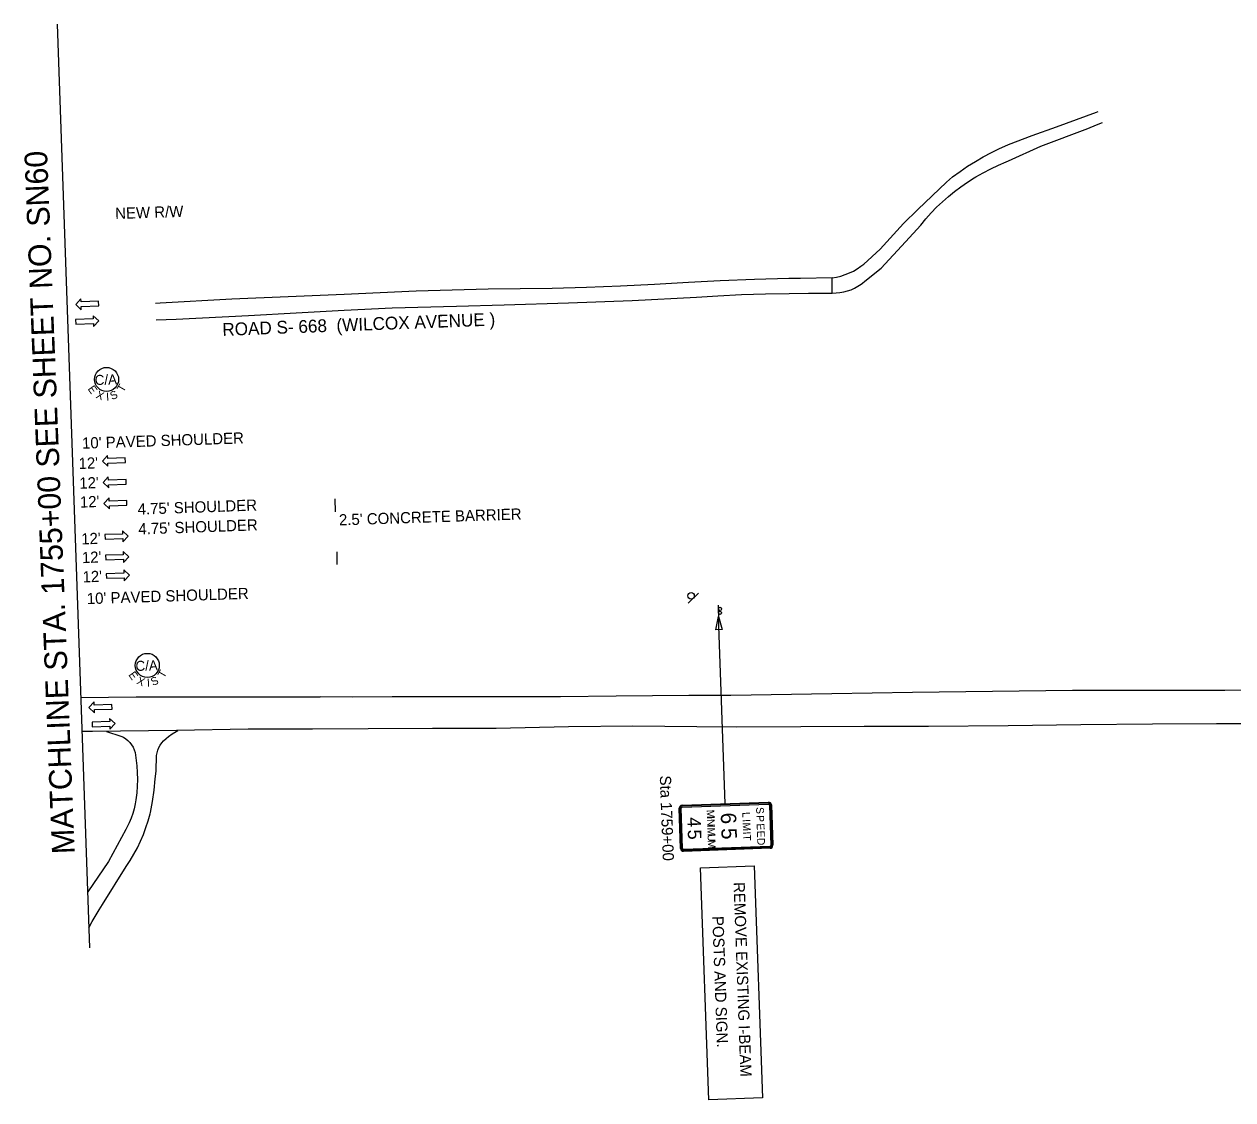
# Model space of a CAD drawing. Extents: x 1821945 to 1823510, y 1192489 to 1193361.
# Drawn here: x 1821945 to 1822700, y 1192504 to 1193176 of the extents above; entities that cross this region are included whole.
import ezdxf

# ---------------------------------------------------------------- set-up
doc = ezdxf.new("R2010")
doc.units = 0
for name, color, linetype in [('RD_EX_Road', 7, 'Continuous'), ('RD_HC_Data_Tic', 7, 'Continuous'), ('RD_HC_Data_Tic_Rel', 7, 'Continuous'), ('RD_PD_Final_LnLine', 7, 'Continuous'), ('RD_PD_Final_TX', 7, 'Continuous'), ('RD_PD_RW_TX', 7, 'Continuous'), ('RD_SHT_MatchLine', 7, 'Continuous'), ('RD_SHT_TX', 7, 'Continuous'), ('RD_Sketch8', 7, 'Continuous'), ('RD_TX_RoadID', 7, 'Continuous'), ('SN_P_Signs', 7, 'Continuous')]:
    doc.layers.add(name, color=color, linetype=linetype)

# ---------------------------------------------------------------- blocks, each defined once
blk = doc.blocks.new('SARRW2')
at = {"layer": 'RD_PD_Final_LnLine'}
blk.add_lwpolyline([(-12, 1.2), (-12, -1.2), (-2.83, -1.2), (-2.83, -2.83), (0, 0), (-2.83, 2.83), (-2.83, 1.2)], close=True, dxfattribs=at)

msp = doc.modelspace()

# ---------------------------------------------------------------- linework, layer by layer
at = {"layer": 'RD_EX_Road'}
for points in [[(1822450.12, 1193017.51), (1822452.87, 1193017.98), (1822455.58, 1193018.65), (1822458.24, 1193019.5), (1822460.83, 1193020.54), (1822463.34, 1193021.75), (1822465.76, 1193023.15), (1822468.08, 1193024.71), (1822469.92, 1193026.13), (1822480.11, 1193035.41), (1822494.72, 1193051.54), (1822503.54, 1193060.25), (1822512.49, 1193068.82), (1822521.58, 1193077.25), (1822525.36, 1193080.68), (1822530, 1193084.04), (1822534.74, 1193087.24), (1822539.59, 1193090.27), (1822544.55, 1193093.13), (1822549.6, 1193095.82), (1822554.74, 1193098.34), (1822559.96, 1193100.67), (1822560.25, 1193100.79), (1822575.06, 1193106.46), (1822590.2, 1193111.91), (1822615.18, 1193120.98), (1822616.32, 1193121.36)], [(1822450.2, 1193008.03), (1822452.59, 1193008.06), (1822454.97, 1193008.28), (1822457.33, 1193008.7), (1822459.64, 1193009.31), (1822461.89, 1193010.11), (1822464.07, 1193011.09), (1822466.16, 1193012.25), (1822468.15, 1193013.58), (1822470.02, 1193015.06), (1822470.45, 1193015.44), (1822480.68, 1193023.45), (1822495.82, 1193039.96), (1822505.43, 1193050.5), (1822508.59, 1193054.33), (1822511.9, 1193058.04), (1822515.36, 1193061.61), (1822518.96, 1193065.05), (1822522.69, 1193068.33), (1822526.54, 1193071.47), (1822530.52, 1193074.45), (1822534.61, 1193077.27), (1822538.82, 1193079.93), (1822539.92, 1193080.59), (1822544.52, 1193083.19), (1822549.22, 1193085.62), (1822554, 1193087.88), (1822558.86, 1193089.96), (1822560.37, 1193090.56), (1822580.39, 1193099.74), (1822609.85, 1193110.81), (1822615.16, 1193113.01), (1822619.02, 1193114.46)], [(1822027.64, 1192991.35), (1822040.23, 1192991.73), (1822085.32, 1192994.01), (1822115.23, 1192995.58), (1822145.29, 1192997.24), (1822175.21, 1192998.81), (1822215.41, 1192999.76), (1822245.26, 1193000.61), (1822285.3, 1193001.87), (1822325.17, 1193003.26), (1822365.26, 1193005.51), (1822378.69, 1193006.33), (1822393.52, 1193007.01), (1822408.35, 1193007.49), (1822423.2, 1193007.77), (1822435.22, 1193007.85), (1822450.2, 1193008.03), (1822450.12, 1193017.51), (1822430.26, 1193017.14), (1822422.93, 1193016.99), (1822401.58, 1193016.41), (1822380.22, 1193015.61), (1822360.26, 1193014.6), (1822339.13, 1193013.27), (1822317.85, 1193012.25), (1822296.55, 1193011.44), (1822275.25, 1193010.82), (1822235.13, 1193010.45), (1822190.13, 1193009.1), (1822145.2, 1193007.04), (1822110.23, 1193005.65), (1822075.09, 1193004.12), (1822030.2, 1193001.63), (1822027.28, 1193001.52)], [(1822130.17, 1192755.54), (1822075.21, 1192755.56), (1822015.25, 1192755.5), (1821980.66, 1192755.06)], [(1822745.23, 1192760.53), (1822695.39, 1192759.67), (1822640.38, 1192759.61), (1822600.23, 1192759.73), (1822550.36, 1192759), (1822500.28, 1192758.44), (1822449.94, 1192757.6), (1822386.84, 1192756.49), (1822360.45, 1192756.46), (1822315.06, 1192756.05), (1822280.31, 1192755.7), (1822245.31, 1192755.75), (1822210.3, 1192755.8), (1822175.21, 1192755.62), (1822150.37, 1192755.53), (1822130.24, 1192755.63)], [(1822720.39, 1192738.89), (1822690.27, 1192738.86), (1822650.16, 1192738.66), (1822605.44, 1192738.13), (1822560.12, 1192737.58), (1822510.19, 1192737.17), (1822470.16, 1192737.23), (1822430.51, 1192737.08), (1822390.42, 1192736.82), (1822365.55, 1192737.06), (1822325.65, 1192737.34), (1822285.35, 1192736.89), (1822240.14, 1192735.99), (1822200.34, 1192735.91), (1822160.28, 1192735.64), (1822125.35, 1192735.6), (1822085.23, 1192735.42), (1822040.4, 1192734.76), (1821987.9, 1192734.12), (1821981.91, 1192734.16), (1821981.4, 1192734.16)], [(1821996.74, 1192734.05), (1822005.67, 1192731.24), (1822007.25, 1192730.44), (1822008.73, 1192729.48), (1822010.09, 1192728.36), (1822011.32, 1192727.09), (1822012.4, 1192725.69), (1822013.31, 1192724.18), (1822014.05, 1192722.58), (1822014.58, 1192721.03), (1822015.65, 1192712.63), (1822015.93, 1192708.39), (1822016.02, 1192704.13), (1822015.91, 1192699.88), (1822015.6, 1192695.64), (1822015.09, 1192691.42), (1822014.69, 1192688.83), (1822014.02, 1192685.77), (1822013.17, 1192682.77), (1822012.12, 1192679.82), (1822010.89, 1192676.94), (1822009.49, 1192674.15), (1822008.76, 1192672.86), (1821997.94, 1192652.83), (1821985, 1192633.8), (1821984.92, 1192633.65)], [(1821985.7, 1192611.4), (1821987.84, 1192615.25), (1821992.19, 1192622.66), (1821994.16, 1192625.9), (1822009, 1192649.74), (1822011.49, 1192653.55), (1822013.82, 1192657.46), (1822015.97, 1192661.47), (1822017.95, 1192665.57), (1822019.74, 1192669.75), (1822021.36, 1192674.01), (1822022.78, 1192678.33), (1822024.02, 1192682.71), (1822024.19, 1192683.35), (1822025.39, 1192690.34), (1822026.39, 1192697.36), (1822027.2, 1192704.4), (1822027.65, 1192709.38), (1822028.03, 1192719.03), (1822028.32, 1192720.75), (1822028.81, 1192722.43), (1822029.48, 1192724.04), (1822030.33, 1192725.57), (1822031.35, 1192727), (1822032.41, 1192728.19), (1822034.01, 1192729.73), (1822035.38, 1192730.86), (1822037.71, 1192732.57), (1822040.15, 1192734.11), (1822041.32, 1192734.77)]]:
    msp.add_lwpolyline(points, dxfattribs=at)
at = {"layer": 'RD_HC_Data_Tic'}
msp.add_line((1822139.77, 1192871.33), (1822139.49, 1192879.33), dxfattribs=at)
at = {"layer": 'RD_HC_Data_Tic_Rel'}
msp.add_line((1822140.91, 1192838.37), (1822140.79, 1192846.37), dxfattribs=at)
at = {"layer": 'RD_SHT_MatchLine'}
msp.add_lwpolyline([(1821965.91, 1193175.99), (1821986.14, 1192598.87)], dxfattribs=at)
at = {"layer": 'RD_Sketch8'}
for centre in [(1821996.75, 1192954.04), (1822022.21, 1192775.37)]:
    msp.add_circle(centre, 7.5, dxfattribs=at)
at = {"layer": 'SN_P_Signs'}
for p, q in [((1822360.21, 1192814.18), (1822366.57, 1192820.54)), ((1822378.89, 1192812.9), (1822379.05, 1192808.41)), ((1822378.96, 1192810.42), (1822379.12, 1192805.92)), ((1822383.27, 1192688.93), (1822379.12, 1192805.92)), ((1822355.44, 1192660.92), (1822354.55, 1192686.11)), ((1822356.29, 1192687.97), (1822410.25, 1192689.88)), ((1822412.11, 1192688.15), (1822413.01, 1192662.96)), ((1822411.27, 1192661.1), (1822357.31, 1192659.19)), ((1822367.87, 1192648.86), (1822401.47, 1192650.05)), ((1822373.01, 1192503.93), (1822367.87, 1192648.86)), ((1822401.47, 1192650.05), (1822406.61, 1192505.13)), ((1822406.61, 1192505.13), (1822373.01, 1192503.93))]:
    msp.add_line(p, q, dxfattribs=at)
msp.add_lwpolyline([(1822377.36, 1192797.65), (1822379.12, 1192805.92), (1822381.46, 1192797.79)], close=True, dxfattribs=at)
for points in [[(1822355.89, 1192660.94), (1822355, 1192686.12)], [(1822356.64, 1192660.96), (1822355.75, 1192686.15)], [(1822356.3, 1192687.52), (1822410.27, 1192689.43)], [(1822356.33, 1192686.77), (1822410.29, 1192688.68)], [(1822410.92, 1192688.11), (1822411.81, 1192662.92)], [(1822411.67, 1192688.13), (1822412.56, 1192662.95)], [(1822411.23, 1192662.3), (1822357.26, 1192660.39)], [(1822411.26, 1192661.55), (1822357.29, 1192659.64)]]:
    msp.add_lwpolyline(points, dxfattribs=at)
for centre, radius in [((1822361.97, 1192818.81), 2), ((1822379.99, 1192810.68), 1), ((1822380.05, 1192808.2), 1)]:
    msp.add_circle(centre, radius, dxfattribs=at)
for centre, radius, start, end in [((1822356.35, 1192686.17), 1.8, 92.03127, 182.03127), ((1822356.35, 1192686.17), 1.35, 92.03127, 182.03127), ((1822356.35, 1192686.17), 0.6, 92.03127, 182.03127), ((1822410.32, 1192688.08), 1.8, 2.03127, 92.03127), ((1822410.32, 1192688.08), 1.35, 2.03127, 92.03127), ((1822410.32, 1192688.08), 0.6, 2.03127, 92.03127), ((1822411.21, 1192662.9), 0.6, 272.03127, 2.03127), ((1822411.21, 1192662.9), 1.35, 272.03127, 2.03127), ((1822411.21, 1192662.9), 1.8, 272.03127, 2.03127), ((1822357.24, 1192660.99), 1.8, 182.03127, 272.03127), ((1822357.24, 1192660.99), 1.35, 182.03127, 272.03127), ((1822357.24, 1192660.99), 0.6, 182.03127, 272.03127)]:
    msp.add_arc(centre, radius, start, end, dxfattribs=at)

# ---------------------------------------------------------------- block references
at = {"layer": 'RD_PD_Final_LnLine'}
for p, xscale, yscale, rotation in [((1821977.45, 1193000.89), 1.2000000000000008, 1.200000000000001, -177.99217052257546), ((1821991.87, 1192990.54), 1.200000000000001, 1.2000000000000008, 2.007829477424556), ((1821994.1, 1192903.02), 1.2000000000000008, 1.200000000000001, -177.99217052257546), ((1821994.57, 1192889.57), 1.2000000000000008, 1.200000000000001, -177.99217052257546), ((1821995.03, 1192876.47), 1.2000000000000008, 1.200000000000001, -177.99217052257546), ((1822010.16, 1192856.12), 1.200000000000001, 1.2000000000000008, 2.007829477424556), ((1822010.61, 1192843.22), 1.200000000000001, 1.2000000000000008, 2.007829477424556), ((1822011.01, 1192831.71), 1.200000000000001, 1.2000000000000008, 2.007829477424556), ((1821985.72, 1192749.05), 1.2000000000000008, 1.200000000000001, -177.99217052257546), ((1822002.14, 1192738.99), 1.200000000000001, 1.2000000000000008, 2.007829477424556)]:
    msp.add_blockref('SARRW2', p, dxfattribs=dict(at, xscale=xscale, yscale=yscale, rotation=rotation))

# ---------------------------------------------------------------- texts
at = {"layer": 'RD_PD_Final_TX'}
for s, rotation, p in [("10' PAVED SHOULDER", 1.88215, (1821981.52, 1192910.72)), ("12'", 2.21446, (1821979.39, 1192898.02)), ("12'", 2.21446, (1821979.82, 1192885.68)), ("12'", 2.21446, (1821980.23, 1192873.89)), ("4.75' SHOULDER", 2.00775, (1822016.27, 1192869.51)), ("2.5' CONCRETE BARRIER", 1.88215, (1822142.06, 1192862.79)), ("4.75' SHOULDER", 2.00775, (1822016.71, 1192857.12)), ("12'", 2.21446, (1821981.04, 1192850.87)), ("12'", 2.21446, (1821981.45, 1192839.2)), ("12'", 2.21446, (1821981.87, 1192827.13)), ("10' PAVED SHOULDER", 1.88215, (1821984.52, 1192813.6))]:
    msp.add_text(s, height=7, rotation=rotation, dxfattribs=at).set_placement(p)
at = {"layer": 'RD_PD_RW_TX'}
msp.add_text('NEW R/W', height=7, rotation=1.87808, dxfattribs=at).set_placement((1822002.22, 1193054.22))
at = {"layer": 'RD_SHT_TX'}
msp.add_text('MATCHLINE STA. 1755+00 SEE SHEET NO. SN60', height=14.1726, rotation=92.25659, dxfattribs=at).set_placement((1821976.83, 1192657.73))
at = {"layer": 'RD_Sketch8'}
for s, height, rotation, p in [('C/A', 6.25, 2.00775, (1821989.46, 1192950.5)), ('E', 5, 305.21899, (1821984.73, 1192948.1)), ('T', 5, 60.19289, (1822007.24, 1192945.69)), ('X', 5, 337.64836, (1821989.71, 1192942.61)), ('I', 5, 1.80836, (1821996.56, 1192940.78)), ('S', 5, 23.80019, (1822000.2, 1192941.08)), ('C/A', 6.25, 2.00775, (1822014.92, 1192771.84)), ('E', 5, 305.21899, (1822010.19, 1192769.43)), ('T', 5, 60.19289, (1822032.7, 1192767.03)), ('X', 5, 337.64836, (1822015.17, 1192763.94)), ('I', 5, 1.80836, (1822022.02, 1192762.11)), ('S', 5, 23.80019, (1822025.66, 1192762.41))]:
    msp.add_text(s, height=height, rotation=rotation, dxfattribs=at).set_placement(p)
at = {"layer": 'RD_TX_RoadID'}
msp.add_text('ROAD S- 668  (WILCOX AVENUE )', height=8, rotation=2.18099, dxfattribs=at).set_placement((1822069.22, 1192981.22))
at = {"layer": 'SN_P_Signs'}
for s, height, rotation, p in [('Sta 1759+00', 7, 272.03135, (1822342.4, 1192706.44)), ('S', 4.8, 272.03127, (1822402.56, 1192686.76)), ('4', 8.4, 272.03127, (1822359.56, 1192680.37)), ('M', 4.8, 272.03127, (1822371.7, 1192685.11)), ('I', 4.8, 272.03127, (1822371.84, 1192680.99)), ('N', 4.8, 272.03127, (1822371.9, 1192679.31)), ('6', 9.6, 272.03127, (1822380.47, 1192683.21)), ('L', 4.8, 272.03127, (1822393.96, 1192683.69)), ('I', 4.8, 272.03127, (1822394.12, 1192679.18)), ('P', 4.8, 272.03127, (1822402.74, 1192681.67)), ('5', 8.4, 272.03127, (1822359.83, 1192672.64)), ('I', 4.8, 272.03127, (1822372.03, 1192675.68)), ('M', 4.8, 272.03127, (1822372.09, 1192673.99)), ('5', 9.6, 272.03127, (1822380.81, 1192673.59)), ('M', 4.8, 272.03127, (1822394.19, 1192677.12)), ('I', 4.8, 272.03127, (1822394.4, 1192671.46)), ('E', 4.8, 272.03127, (1822402.92, 1192676.57)), ('E', 4.8, 272.03127, (1822403.08, 1192672.03)), ('U', 4.8, 272.03127, (1822372.24, 1192669.87)), ('M', 4.8, 272.03127, (1822372.37, 1192666.24)), ('T', 4.8, 272.03127, (1822394.46, 1192669.65)), ('D', 4.8, 272.03127, (1822403.24, 1192667.49)), ('REMOVE EXISTING I-BEAM', 6.9998, 272.03135, (1822388.46, 1192639.84)), ('POSTS AND SIGN. ', 6.9998, 272.03135, (1822375.2, 1192618.65))]:
    msp.add_text(s, height=height, rotation=rotation, dxfattribs=at).set_placement(p)

doc.saveas('drawing.dxf')
